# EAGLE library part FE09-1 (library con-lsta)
FEMALE HEADER
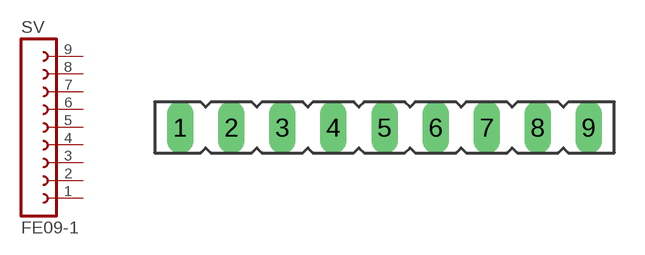
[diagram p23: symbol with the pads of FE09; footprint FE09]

Designator prefix SV

## FE09-1 (OC_FARNELL: unknown; OC_NEWARK: unknown)  [FE09]
1  1  pas
2  2  pas
3  3  pas
4  4  pas
5  5  pas
6  6  pas
7  7  pas
8  8  pas
9  9  pas

## Footprint FE09 (pad centres in mm)
FEMALE HEADER
drill 0.813 long: 1 -10.16,0; 2 -7.62,0; 3 -5.08,0; 4 -2.54,0; 5 0,0; 6 2.54,0; 7 5.08,0; 8 7.62,0; 9 10.16,0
